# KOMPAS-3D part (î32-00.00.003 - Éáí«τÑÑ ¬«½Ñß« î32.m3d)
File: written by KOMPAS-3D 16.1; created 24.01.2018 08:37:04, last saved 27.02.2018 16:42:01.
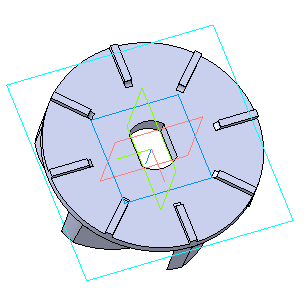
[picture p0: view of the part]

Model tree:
1. Операция без истории:1
2. Смещенная плоскость:1
     Расстояние = 5
3. Эскиз:1
4. Вырезать элемент выдавливания:1
     Расстояние 2 = 31; Расстояние 1 = 13
5. Эскиз:2
6. Вырезать элемент выдавливания:2  (labels: М32-00.00.003)
     Расстояние 2 = 20; Расстояние 1 = 13

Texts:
  Рабочее колесо М32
